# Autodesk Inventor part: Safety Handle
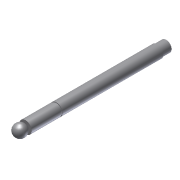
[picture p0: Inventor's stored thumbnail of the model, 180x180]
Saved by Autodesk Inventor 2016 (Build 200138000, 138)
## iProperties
Shininess: 77.0
Length Units: 11269
Angle Units: 11279
Time Units: 11290
Mass Units: 11283
Length Display Precision: 3
Angle Display Precision: 2
Created: 2002-02
Part Number: Safety Handle
Document SubType Name: Modeling
Designer: ***
Density: 1 g/cm^3
Material: Generic
Appearance: Default
Density: 0.0
Volumn: 0.0
Area: 0.0
PropertySet Name: Model Information
Control State: 0
Master: False
Checked Out: False
Author: ***
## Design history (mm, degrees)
sketch "Sketch1"
  geometry: L1 (0, 205)-(8, 205); L2 (8, 205)-(8, 192); L3 (8, 192)-(9, 192); L4 (9, 192)-(9, 45); L5 (9, 45)-(8, 45); L6 (8, 45)-(8, 43); L7 (8, 43)-(9, 43); L8 (9, 43)-(9, 0); L9 (9, 0)-(0, 0); L10 (0, 0)-(0, 205)
  constraints: 20 end point, 7 parallel, 1 collinear, 1 horizontal, 1 perpendicular
  dimensions: "d0" = 13 distance of L1.end L2.end; "d1" = 2 distance of L4.end L7.end; "d2" = 43 distance of L7.end L8.end; "d3" = 205 distance of L9.end L1.start; "d4" = 16 diameter of L2 L10; "d5" = 18 diameter of L4 L10; "d6" = 16 diameter of L6.end L10
revolve "Revolution1" sketch "Sketch1" stored, may be unused: angle "d7" = 90 deg
sketch "Sketch2"
  geometry: L1 (0, 1)-(0, -17); L2 (-9, 0)-(9, 0) reference; A1 r 9 centre (0, -8) between (0, -17) and (0, 1)
  constraints: 2 end point, 2 point on circle, 1 centre point, 1 midpoint, 1 vertical
  dimensions: "d8" = 9 radius of A1; "d9" = 1 distance from line of L2 L1.start
revolve "Revolution2" sketch "Sketch2" stored, may be unused: angle "d10" = 90 deg
body "Solid1"
